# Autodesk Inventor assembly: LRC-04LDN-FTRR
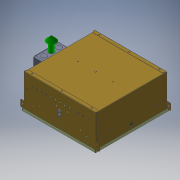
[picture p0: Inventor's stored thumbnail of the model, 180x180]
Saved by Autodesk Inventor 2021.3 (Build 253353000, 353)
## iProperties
description: 0:0:Regressed lens 4" Downlight - COB LED
manufacturer: 0:0:The Kirlin Company
model: 0:0:LRC-04LDN
url: 0:0:
load_classification: Lighting
motor: 0 ul
Part Number: LRC-04LDN-FTRR
Document SubType Name: Assembly
Designer: JChurch
Author: JChurch
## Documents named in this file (5)
- X:\Revit Files\0000-Un-Zipped\COB\LRC-04LDN-FTR\LRC-04LDN-FTRR.iam
- X:\INVENTOR\830\830520-00-00.ipt
- X:\INVENTOR\881\881088-00-00.iam
- X:\INVENTOR\750\750480-FT-XX.iam
- X:\Revit Files\0000-Un-Zipped\COB\LRC-04LDN-FTR\LRC-04LDN-FTRR_Substitute_1.ipt
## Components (4 placed, 4 different names)
1. 830520-00-00:1 — Mate:1, Mate:2, Mate:3, Mate:4, Tangent:1, Angle:1, Insert:1
2. 881088-00-00:1 [sub-assembly] — Mate:4, Tangent:1, Angle:1
3. 750480-FT-XX:1 [sub-assembly] — Insert:1
4. LRC-04LDN-FTRR_Substitute_1:1
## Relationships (7: Mate 4, Tangent 1, Angle 1, Insert 1)
- Mate:1: 830520-00-00:1
- Mate:2: 830520-00-00:1
- Mate:3: 830520-00-00:1
- Mate:4: 830520-00-00:1 ↔ 881088-00-00:1
- Tangent:1: 830520-00-00:1 ↔ 881088-00-00:1
- Angle:1: 830520-00-00:1 ↔ 881088-00-00:1
- Insert:1: 830520-00-00:1 ↔ 750480-FT-XX:1
